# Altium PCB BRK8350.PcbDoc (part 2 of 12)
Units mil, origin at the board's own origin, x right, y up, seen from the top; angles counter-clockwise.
Board outline 9448.82 x 5905.51 mil, 8 copper layers (L1-TOP, L2-GND, L3-SIG, L4-GND, L5-PWR, L6-PWR, L7-GND, L8-BOT), stack 57.69 mil thick; 288 components, 543 nets, 1891 pads, 2032 vias.
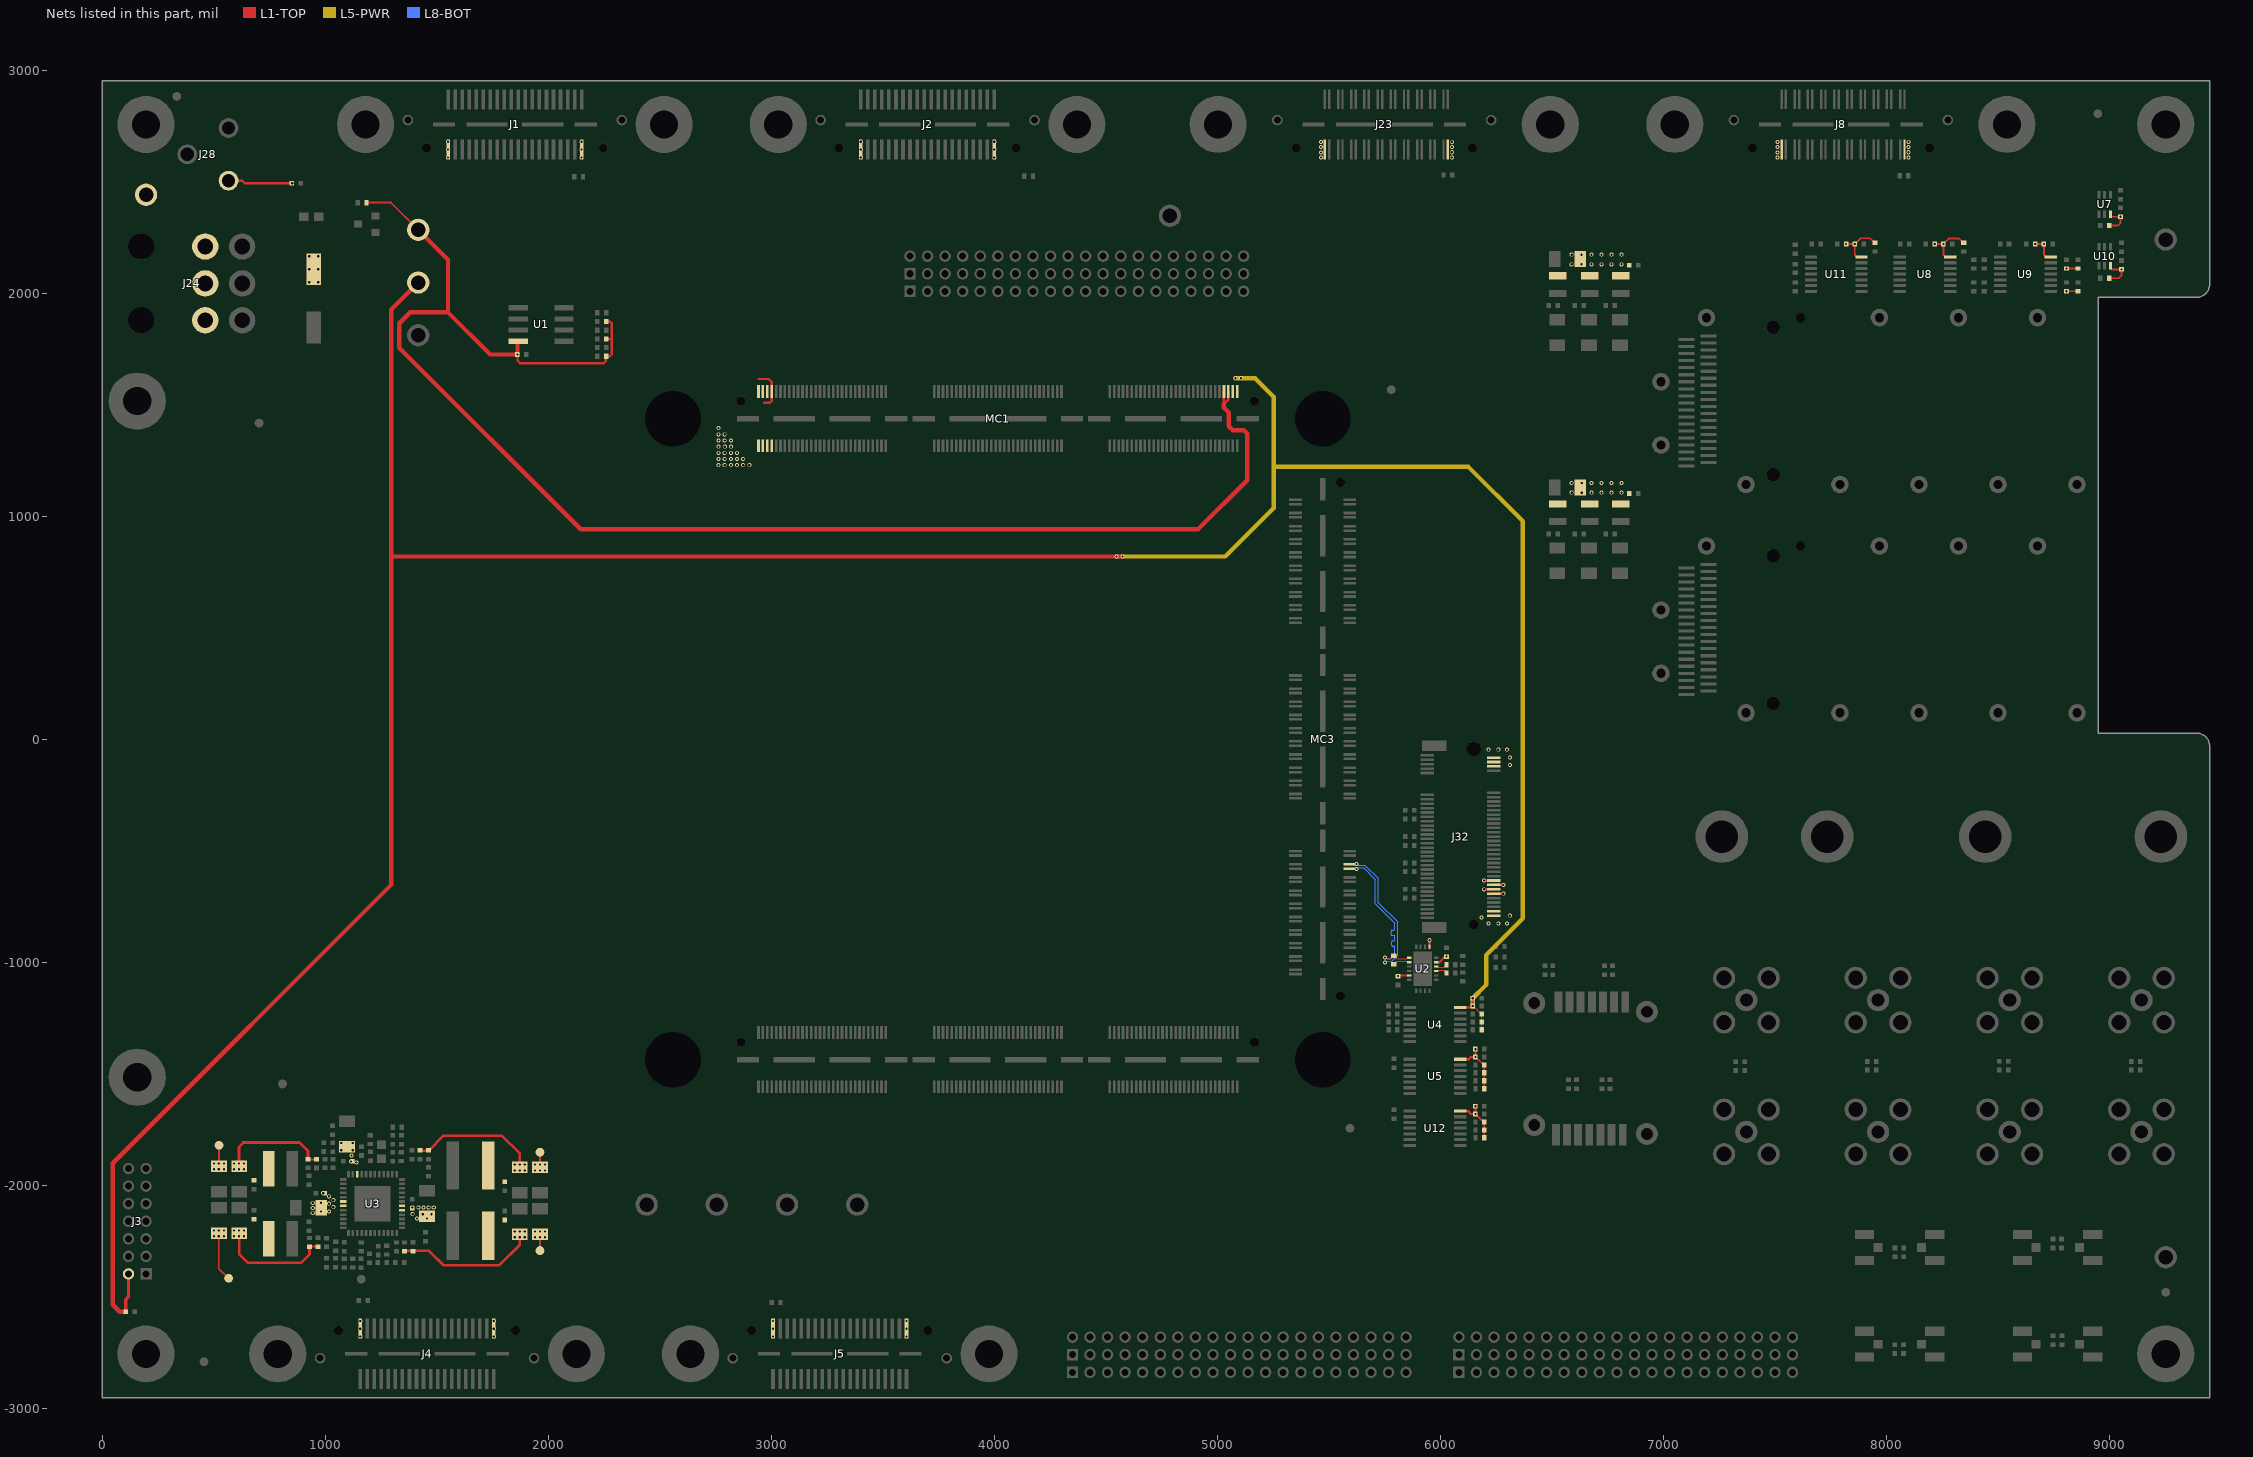
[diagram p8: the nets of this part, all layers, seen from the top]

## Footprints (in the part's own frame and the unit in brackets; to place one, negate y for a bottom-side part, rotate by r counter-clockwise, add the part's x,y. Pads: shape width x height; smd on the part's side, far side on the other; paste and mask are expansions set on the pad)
0455580003 [mm]
  round 3 hole 3 unplated: 0(-4.2,7.3) 0(4.2,7.3)
  round 3 hole 1.8: 1(-4.2,0) 2(0,0) 3(4.2,0) 4(-4.2,-4.2) 5(0,-4.2) 6(4.2,-4.2)
  silkscreen extent -7,1 7,14
9774025151R [mm]
  round 6 hole 3.7: 1(0,0)
9774025151R-NO-PASTE [mm]
  round 6 hole 3.7: 1(0,0)
CAPAE9083X70N [mm] "Aluminum Electrolytic Capacitor, Body 8.30x8.30x7.00mm, IPC Medium Density"
  rect 3.6x1.65 smd: 1(-3.325,0) 2(3.325,0)
  silkscreen extent -4.25,-4.25 4.25,4.25
CAPC1005X06A#1 [mm] "Chip Capacitor, 2-Leads, Body 1.00x0.50mm, OK custom footprint"
  rect 0.52x0.55 smd mask+0.051: 1(-0.51,0) 2(0.51,0)
CAPC1005X06A#2 [mm] "Chip Capacitor, 2-Leads, Body 1.00x0.50mm, OK custom footprint"
  rect 0.52x0.55 smd: 1(-0.51,0) 2(0.51,0)
CAPC1608N [mm] "Chip Capacitor, Body 1.6x0.8mm, IPC Medium Density"
  rect 1x1 smd: 1(-0.8,0) 2(0.8,0)
  silkscreen extent -0.8,-0.68 0.8,0.68, body extent -0.87,-0.48 0.87,0.48, height 0.85
CAPC3216N [mm] "Chip Capacitor, Body 3.2x1.6mm, IPC Medium Density"
  rect 1.3x1.8 smd: 1(-1.45,0) 2(1.45,0)
  silkscreen extent -1.2,-1.08 1.2,1.08, body extent -1.7,-0.9 1.7,0.9, height 1.35
CD1608-0603-PIN1-CATHODE [mm] "Chip Diode; Body 1.6 x 0.8 mm (LxW typ)"
  rect 1.1x1 smd: 1(-0.85,0) 2(0.85,0)
  silkscreen extent -1.58,-0.68 0.6,0.68
CIGT252010 [mm]
  rect 0.8x2 smd: 1(-1,0) 2(1,0)
CUI-PJ102A [mm] "2.1mm/5.5mm DC power jack"
  round 2.25 hole 1.5: 1(0,13.7) 2(0,7.7) 3(4.7,10.7)
  silkscreen extent -4.5,0 4.5,14.5
DCK-R-PDSO-G6 [mm]
  rect 0.35x0.85 smd: 1(-0.65,-1.1) 2(0,-1.1) 3(0.65,-1.1) 4(0.65,1.1) 5(0,1.1) 6(-0.65,1.1)
  silkscreen extent -1.01,-1.55 1.01,0.65
DSC557-05 [mm]
  rect 0.5x0.25 smd: 1(-2.5,0.75) 2(-2.5,0.25) 3(-2.5,-0.25) 4(-2.5,-0.75) 11(2.5,-0.75) 12(2.5,-0.25) 13(2.5,0.25) 14(2.5,0.75)
  rect 0.25x0.5 smd: 5(-1.25,-1.55) 6(-0.75,-1.55) 7(-0.25,-1.55) 8(0.25,-1.55) 9(0.75,-1.55) 10(1.25,-1.55) 15(1.25,1.55) 16(0.75,1.55) 17(0.25,1.55) 18(-0.25,1.55) 19(-0.75,1.55) 20(-1.25,1.55)
  rect 3.9x2.1 smd paste-10: PAD(0,0)
  silkscreen extent -2.9,-1.65 2.55,2
FID1MM/2MM-SS [mm] "Fiducial 1mm copper, 2mm soldermask, single-side"
  round 1 smd paste-0.5 mask+0.5: FID?(0,0)
HDR1X20-2MM [mm] "2mm 1x20 Header"
  rect 1.3x1.3 hole 0.8: 1(-19,0)
  round 1.3 hole 0.8: 2(-17,0) 3(-15,0) 4(-13,0) 5(-11,0) 6(-9,0) 7(-7,0) 8(-5,0) 9(-3,0) 10(-1,0) 11(1,0) 12(3,0) 13(5,0) 14(7,0) 15(9,0) 16(11,0) 17(13,0) 18(15,0) 19(17,0) 20(19,0)
  silkscreen extent -20,-1 20,1
HDR2X20-2MM [mm] "2mm 2x20 header"
  rect 1.3x1.3 hole 0.8: 1(-19,-1)
  round 1.3 hole 0.8: 2(-19,1) 3(-17,-1) 4(-17,1) 5(-15,-1) 6(-15,1) 7(-13,-1) 8(-13,1) 9(-11,-1) 10(-11,1) 11(-9,-1) 12(-9,1) 13(-7,-1) 14(-7,1) 15(-5,-1) 16(-5,1) 17(-3,-1) 18(-3,1) 19(-1,-1) 20(-1,1) 21(1,-1) 22(1,1) 23(3,-1) 24(3,1) 25(5,-1) 26(5,1) 27(7,-1) 28(7,1) 29(9,-1) 30(9,1) 31(11,-1) 32(11,1) 33(13,-1) 34(13,1) 35(15,-1) 36(15,1) 37(17,-1) 38(17,1) 39(19,-1) 40(19,1)
  silkscreen extent -20,-2 20,2
JSO-0515-01 [mil]
  round 0 hole 250 unplated: 1(0,0)
  Keep-Out Layer region: 0,-157.48 -60.27,-145.49 -111.36,-111.36 -145.49,-60.27 -157.48,0 -157.48,0 -145.49,60.27 -111.36,111.36 -60.27,145.49 0,157.48 0,157.48 60.27,145.49 111.36,111.36 145.49,60.27 157.48,0 157.48,0 145.49,-60.27 111.36,-111.36 60.27,-145.49 0,-157.48
M2-CONNECTOR_M-KEYING [mm] "M-2 Connector, 67-pin, M Keying"
  rect 1.2x2.75 smd mask+0.051: 1(-10.35,4.5) 1(10.35,4.5)
  rect 0.3x1.55 smd mask+0.051: 1(-9.25,5.275) 2(-9,-2.275) 3(-8.75,5.275) 4(-8.5,-2.275) 5(-8.25,5.275) 6(-8,-2.275) 7(-7.75,5.275) 8(-7.5,-2.275) 9(-7.25,5.275) 10(-7,-2.275) 11(-6.75,5.275) 12(-6.5,-2.275) 13(-6.25,5.275) 14(-6,-2.275) 15(-5.75,5.275) 16(-5.5,-2.275) 17(-5.25,5.275) 18(-5,-2.275) 19(-4.75,5.275) 20(-4.5,-2.275) 21(-4.25,5.275) 22(-4,-2.275) 23(-3.75,5.275) 24(-3.5,-2.275) 25(-3.25,5.275) 26(-3,-2.275) 27(-2.75,5.275) 28(-2.5,-2.275) 29(-2.25,5.275) 30(-2,-2.275) 31(-1.75,5.275) 32(-1.5,-2.275) 33(-1.25,5.275) 34(-1,-2.275) 35(-0.75,5.275) 36(-0.5,-2.275) 37(-0.25,5.275) 38(0,-2.275) 39(0.25,5.275) 40(0.5,-2.275) 41(0.75,5.275) 42(1,-2.275) 43(1.25,5.275) 44(1.5,-2.275) 45(1.75,5.275) 46(2,-2.275) 47(2.25,5.275) 48(2.5,-2.275) 49(2.75,5.275) 50(3,-2.275) 51(3.25,5.275) 52(3.5,-2.275) 53(3.75,5.275) 54(4,-2.275) 55(4.25,5.275) 56(4.5,-2.275) 57(4.75,5.275) 58(5,-2.275) 67(7.25,5.275) 68(7.5,-2.275) 69(7.75,5.275) 70(8,-2.275) 71(8.25,5.275) 72(8.5,-2.275) 73(8.75,5.275) 74(9,-2.275) 75(9.25,5.275)
  round 1.1 hole 1.1 unplated paste+0: MH(-10,0)
  round 1.6 hole 1.6 unplated paste+0: MH(10,0)
  silkscreen extent -11,-2.55 11,5.3
MAX3378EEUD+ [mm]
  rect 0.35x1.4 smd: 1(-1.95,-2.875) 2(-1.3,-2.875) 3(-0.65,-2.875) 4(0,-2.875) 5(0.65,-2.875) 6(1.3,-2.875) 7(1.95,-2.875) 8(1.95,2.875) 9(1.3,2.875) 10(0.65,2.875) 11(0,2.875) 12(-0.65,2.875) 13(-1.3,2.875) 14(-1.95,2.875)
  silkscreen extent -2.55,-3.83 2.55,2.27
MOLEX-67800-5005 [mm]
  rect 0.9x2.4 smd: 1(3.955,0.55) 2(2.685,0.55) 3(1.415,0.55) 4(0.145,0.55) 5(-1.125,0.55) 6(-2.395,0.55) 7(-3.665,0.55)
  round 2.5 hole 1.35: MH(-6.415,0.45) MH(6.415,-0.55)
  silkscreen extent -8.65,-3.9 8.6,2.85
MTG-3.2/6.5-PTH [mm] "Mounting hole, 3.2mm ID, 6.5mm OD, plated"
  round 6.5 hole 3.2: 1(0,0)
okLogo-23x5-2021 [mil] "Opal Kelly silkscreen logo (23mm x 5mm) - 2021 update"
  silkscreen extent -4,-15 672,100
PVQFN-48 [mm]
  rect 0.7x0.3 smd mask+0.051: 1(-3.35,2.75) 2(-3.35,2.25) 3(-3.35,1.75) 4(-3.35,1.25) 5(-3.35,0.75) 6(-3.35,0.25) 7(-3.35,-0.25) 8(-3.35,-0.75) 9(-3.35,-1.25) 10(-3.35,-1.75) 11(-3.35,-2.25) 12(-3.35,-2.75) 25(3.35,-2.75) 26(3.35,-2.25) 27(3.35,-1.75) 28(3.35,-1.25) 29(3.35,-0.75) 30(3.35,-0.25) 31(3.35,0.25) 32(3.35,0.75) 33(3.35,1.25) 34(3.35,1.75) 35(3.35,2.25) 36(3.35,2.75)
  rect 0.3x0.7 smd mask+0.051: 13(-2.75,-3.35) 14(-2.25,-3.35) 15(-1.75,-3.35) 16(-1.25,-3.35) 17(-0.75,-3.35) 18(-0.25,-3.35) 19(0.25,-3.35) 20(0.75,-3.35) 21(1.25,-3.35) 22(1.75,-3.35) 23(2.25,-3.35) 24(2.75,-3.35) 37(2.75,3.35) 38(2.25,3.35) 39(1.75,3.35) 40(1.25,3.35) 41(0.75,3.35) 42(0.25,3.35) 43(-0.25,3.35) 44(-0.75,3.35) 45(-1.25,3.35) 46(-1.75,3.35) 47(-2.25,3.35) 48(-2.75,3.35)
  rect 4.08x4.08 smd mask+0.051: PAD(0,0)
  silkscreen extent -3.89,-3.6 3.6,3.89
QSE-020-01-X-D-A-L-SYZYGY [mil] "0.80mm, 40 pin Surface Mount connectors with Ground Strip"
  rect 100x17 smd paste+0: 0(-317.45,0) 0(317.55,0)
  rect 185x17 smd paste+0: 0(-124.95,0) 0(125.05,0)
  round 255.91 hole 125.98: 1(-669.24,0) 1(669.34,0)
  rect 16x89.5 smd paste+0: 1(-299.25,-112.8) 2(-299.25,112.8) 3(-267.75,-112.8) 4(-267.75,112.8) 5(-236.25,-112.8) 6(-236.25,112.8) 7(-204.75,-112.8) 8(-204.75,112.8) 9(-173.25,-112.8) 10(-173.25,112.8) 11(-141.75,-112.8) 12(-141.75,112.8) 13(-110.25,-112.8) 14(-110.25,112.8) 15(-78.75,-112.8) 16(-78.75,112.8) 17(-47.25,-112.8) 18(-47.25,112.8) 19(-15.75,-112.8) 20(-15.75,112.8) 21(15.75,-112.8) 22(15.75,112.8) 23(47.25,-112.8) 24(47.25,112.8) 25(78.75,-112.8) 26(78.75,112.8) 27(110.25,-112.8) 28(110.25,112.8) 29(141.75,-112.8) 30(141.75,112.8) 31(173.25,-112.8) 32(173.25,112.8) 33(204.75,-112.8) 34(204.75,112.8) 35(236.25,-112.8) 36(236.25,112.8) 37(267.75,-112.8) 38(267.75,112.8) 39(299.25,-112.8) 40(299.25,112.8)
  round 47.24 hole 31.5 paste+0: MH(-479.48,-19.69) MH(479.58,-19.69)
  round 40.16 hole 40.16 unplated paste+0: MH(-396.25,105) MH(396.35,105)
  silkscreen extent -886,-157 885,276
QSFP28_RECEPTACLE_SFF-8679 [mm]
  rect 0.35x1.8 smd: 1(1.4,7.37) 2(2.2,7.37) 3(3,7.37) 4(3.8,7.37) 5(4.6,7.37) 6(5.4,7.37) 7(6.2,7.37) 8(7,7.37) 9(7.8,7.37) 10(8.6,7.37) 11(9.4,7.37) 12(10.2,7.37) 13(11,7.37) 14(11.8,7.37) 15(12.6,7.37) 16(13.4,7.37) 17(14.2,7.37) 18(15,7.37) 19(15.8,7.37) 20(15.4,9.88) 21(14.6,9.88) 22(13.8,9.88) 23(13,9.88) 24(12.2,9.88) 25(11.4,9.88) 26(10.6,9.88) 27(9.8,9.88) 28(9,9.88) 29(8.2,9.88) 30(7.4,9.88) 31(6.6,9.88) 32(5.8,9.88) 33(5,9.88) 34(4.2,9.88) 35(3.4,9.88) 36(2.6,9.88) 37(1.8,9.88) 38(1,9.88)
  round 1.55 hole 1.55 unplated: MH(0,0) MH(16.8,0)
  L1-TOP keep-out region: 16.3,-3.16 17.3,-3.16 17.3,-2.16 16.3,-2.16
  L1-TOP keep-out region: -0.5,-3.16 0.5,-3.16 0.5,-2.16 -0.5,-2.16
  silkscreen extent -0.8,-3 17.6,9.7
QSFP28_SINGLE_CAGE [mm]
  round 2 hole 1.05: 0(-1.1,3.1) 0(-1.1,-7.6) 0(-1.1,-16.6) 0(-1.1,-25.6) 0(-1.1,-34.6) 0(3.4,12.79) 0(10.6,12.79) 0(17.9,-21.1) 0(17.9,-12.1) 0(17.9,7.6) 0(17.9,-30.1)
  round 0 hole 1.05 unplated: 0(17.9,-3.1)
  L1-TOP keep-out region: -2.7,13.5 -2.7,-37 19.5,-37 19.5,13.5 16.5,13.5 16.5,11.1 18,11.1 18,-1.6 15.9,-1.6 15.9,-3.5 0.9,-3.5 0.9,-1.6 -1.2,-1.6 -1.2,11.1 0.3,11.1 0.3,13.5
  silkscreen extent -1.1,-48.2 17.9,12.9
QSH-020-01-X-D-DP-A-L-SYZYGY [mm]
  rect 2.54x0.43 smd mask+0.051: 0(-8.07,0) 0(8.06,0)
  rect 4.7x0.43 smd mask+0.051: 0(-3.18,0) 0(3.17,0)
  round 6.5 hole 3.2: 1(-18.909,0) 1(18.911,0)
  rect 0.28x2.27 smd mask+0.051: 1(-7.25,-2.87) 2(-7.25,2.87) 3(-6.75,-2.87) 4(-6.75,2.87) 5(-5.75,-2.87) 6(-5.75,2.87) 7(-5.25,-2.87) 8(-5.25,2.87) 9(-4.25,-2.87) 10(-4.25,2.87) 11(-3.75,-2.87) 12(-3.75,2.87) 13(-2.75,-2.87) 14(-2.75,2.87) 15(-2.25,-2.87) 16(-2.25,2.87) 17(-1.25,-2.87) 18(-1.25,2.87) 19(-0.75,-2.87) 20(-0.75,2.87) 21(0.25,-2.87) 22(0.25,2.87) 23(0.75,-2.87) 24(0.75,2.87) 25(1.75,-2.87) 26(1.75,2.87) 27(2.25,-2.87) 28(2.25,2.87) 29(3.25,-2.87) 30(3.25,2.87) 31(3.75,-2.87) 32(3.75,2.87) 33(4.75,-2.87) 34(4.75,2.87) 35(5.25,-2.87) 36(5.25,2.87) 37(6.25,-2.87) 38(6.25,2.87) 39(6.75,-2.87) 40(6.75,2.87)
  round 1.2 hole 0.8 paste+0 mask+0.076: MH(-12.18,-0.5) MH(12.18,-0.5)
  round 1.02 hole 1.02 unplated paste+0: MH(-10.07,2.67) MH(10.07,2.67)
  silkscreen extent -25,-3.99 25,7.01
QTH-060-01-X-D-DP-A [mm] "2mm 1x20 Header"
  rect 2.54x0.64 smd: 0(-28.445,0) 0(-11.555,0) 0(-8.445,0) 0(8.445,0) 0(11.555,0) 0(28.445,0)
  rect 4.7x0.64 smd: 0(-23.175,0) 0(-16.825,0) 0(-3.175,0) 0(3.175,0) 0(16.825,0) 0(23.175,0)
  rect 0.3x1.45 smd: 1(-27.25,3.09) 2(-27.25,-3.09) 3(-26.75,3.09) 4(-26.75,-3.09) 5(-25.75,3.09) 6(-25.75,-3.09) 7(-25.25,3.09) 8(-25.25,-3.09) 9(-24.25,3.09) 10(-24.25,-3.09) 11(-23.75,3.09) 12(-23.75,-3.09) 13(-22.75,3.09) 14(-22.75,-3.09) 15(-22.25,3.09) 16(-22.25,-3.09) 17(-21.25,3.09) 18(-21.25,-3.09) 19(-20.75,3.09) 20(-20.75,-3.09) 21(-19.75,3.09) 22(-19.75,-3.09) 23(-19.25,3.09) 24(-19.25,-3.09) 25(-18.25,3.09) 26(-18.25,-3.09) 27(-17.75,3.09) 28(-17.75,-3.09) 29(-16.75,3.09) 30(-16.75,-3.09) 31(-16.25,3.09) 32(-16.25,-3.09) 33(-15.25,3.09) 34(-15.25,-3.09) 35(-14.75,3.09) 36(-14.75,-3.09) 37(-13.75,3.09) 38(-13.75,-3.09) 39(-13.25,3.09) 40(-13.25,-3.09) 41(-7.25,3.09) 42(-7.25,-3.09) 43(-6.75,3.09) 44(-6.75,-3.09) 45(-5.75,3.09) 46(-5.75,-3.09) 47(-5.25,3.09) 48(-5.25,-3.09) 49(-4.25,3.09) 50(-4.25,-3.09) 51(-3.75,3.09) 52(-3.75,-3.09) 53(-2.75,3.09) 54(-2.75,-3.09) 55(-2.25,3.09) 56(-2.25,-3.09) 57(-1.25,3.09) 58(-1.25,-3.09) 59(-0.75,3.09) 60(-0.75,-3.09) 61(0.25,3.09) 62(0.25,-3.09) 63(0.75,3.09) 64(0.75,-3.09) 65(1.75,3.09) 66(1.75,-3.09) 67(2.25,3.09) 68(2.25,-3.09) 69(3.25,3.09) 70(3.25,-3.09) 71(3.75,3.09) 72(3.75,-3.09) 73(4.75,3.09) 74(4.75,-3.09) 75(5.25,3.09) 76(5.25,-3.09) 77(6.25,3.09) 78(6.25,-3.09) 79(6.75,3.09) 80(6.75,-3.09) 81(12.75,3.09) 82(12.75,-3.09) 83(13.25,3.09) 84(13.25,-3.09) 85(14.25,3.09) 86(14.25,-3.09) 87(14.75,3.09) 88(14.75,-3.09) 89(15.75,3.09) 90(15.75,-3.09) 91(16.25,3.09) 92(16.25,-3.09) 93(17.25,3.09) 94(17.25,-3.09) 95(17.75,3.09) 96(17.75,-3.09) 97(18.75,3.09) 98(18.75,-3.09) 99(19.25,3.09) 100(19.25,-3.09) 101(20.25,3.09) 102(20.25,-3.09) 103(20.75,3.09) 104(20.75,-3.09) 105(21.75,3.09) 106(21.75,-3.09) 107(22.25,3.09) 108(22.25,-3.09) 109(23.25,3.09) 110(23.25,-3.09) 111(23.75,3.09) 112(23.75,-3.09) 113(24.75,3.09) 114(24.75,-3.09) 115(25.25,3.09) 116(25.25,-3.09) 117(26.25,3.09) 118(26.25,-3.09) 119(26.75,3.09) 120(26.75,-3.09)
  round 1.02 hole 1.02 unplated: MH(-29.24,2.03) MH(29.24,2.03)
  silkscreen extent -30.05,-3.05 30.05,3.05
QTH-090-01-X-D [mm]
  rect 2.54x0.64 smd: 0(-28.445,0) 0(-11.555,0) 0(-8.445,0) 0(8.445,0) 0(11.555,0) 0(28.445,0)
  rect 4.7x0.64 smd: 0(-23.175,0) 0(-16.825,0) 0(-3.175,0) 0(3.175,0) 0(16.825,0) 0(23.175,0)
  rect 0.3x1.45 smd: 1(-27.25,3.09) 2(-27.25,-3.09) 3(-26.75,3.09) 4(-26.75,-3.09) 5(-26.25,3.09) 6(-26.25,-3.09) 7(-25.75,3.09) 8(-25.75,-3.09) 9(-25.25,3.09) 10(-25.25,-3.09) 11(-24.75,3.09) 12(-24.75,-3.09) 13(-24.25,3.09) 14(-24.25,-3.09) 15(-23.75,3.09) 16(-23.75,-3.09) 17(-23.25,3.09) 18(-23.25,-3.09) 19(-22.75,3.09) 20(-22.75,-3.09) 21(-22.25,3.09) 22(-22.25,-3.09) 23(-21.75,3.09) 24(-21.75,-3.09) 25(-21.25,3.09) 26(-21.25,-3.09) 27(-20.75,3.09) 28(-20.75,-3.09) 29(-20.25,3.09) 30(-20.25,-3.09) 31(-19.75,3.09) 32(-19.75,-3.09) 33(-19.25,3.09) 34(-19.25,-3.09) 35(-18.75,3.09) 36(-18.75,-3.09) 37(-18.25,3.09) 38(-18.25,-3.09) 39(-17.75,3.09) 40(-17.75,-3.09) 41(-17.25,3.09) 42(-17.25,-3.09) 43(-16.75,3.09) 44(-16.75,-3.09) 45(-16.25,3.09) 46(-16.25,-3.09) 47(-15.75,3.09) 48(-15.75,-3.09) 49(-15.25,3.09) 50(-15.25,-3.09) 51(-14.75,3.09) 52(-14.75,-3.09) 53(-14.25,3.09) 54(-14.25,-3.09) 55(-13.75,3.09) 56(-13.75,-3.09) 57(-13.25,3.09) 58(-13.25,-3.09) 59(-12.75,3.09) 60(-12.75,-3.09) 61(-7.25,3.09) 62(-7.25,-3.09) 63(-6.75,3.09) 64(-6.75,-3.09) 65(-6.25,3.09) 66(-6.25,-3.09) 67(-5.75,3.09) 68(-5.75,-3.09) 69(-5.25,3.09) 70(-5.25,-3.09) 71(-4.75,3.09) 72(-4.75,-3.09) 73(-4.25,3.09) 74(-4.25,-3.09) 75(-3.75,3.09) 76(-3.75,-3.09) 77(-3.25,3.09) 78(-3.25,-3.09) 79(-2.75,3.09) 80(-2.75,-3.09) 81(-2.25,3.09) 82(-2.25,-3.09) 83(-1.75,3.09) 84(-1.75,-3.09) 85(-1.25,3.09) 86(-1.25,-3.09) 87(-0.75,3.09) 88(-0.75,-3.09) 89(-0.25,3.09) 90(-0.25,-3.09) 91(0.25,3.09) 92(0.25,-3.09) 93(0.75,3.09) 94(0.75,-3.09) 95(1.25,3.09) 96(1.25,-3.09) 97(1.75,3.09) 98(1.75,-3.09) 99(2.25,3.09) 100(2.25,-3.09) 101(2.75,3.09) 102(2.75,-3.09) 103(3.25,3.09) 104(3.25,-3.09) 105(3.75,3.09) 106(3.75,-3.09) 107(4.25,3.09) 108(4.25,-3.09) 109(4.75,3.09) 110(4.75,-3.09) 111(5.25,3.09) 112(5.25,-3.09) 113(5.75,3.09) 114(5.75,-3.09) 115(6.25,3.09) 116(6.25,-3.09) 117(6.75,3.09) 118(6.75,-3.09) 119(7.25,3.09) 120(7.25,-3.09) 121(12.75,3.09) 122(12.75,-3.09) 123(13.25,3.09) 124(13.25,-3.09) 125(13.75,3.09) 126(13.75,-3.09) 127(14.25,3.09) 128(14.25,-3.09) 129(14.75,3.09) 130(14.75,-3.09) 131(15.25,3.09) 132(15.25,-3.09) 133(15.75,3.09) 134(15.75,-3.09) 135(16.25,3.09) 136(16.25,-3.09) 137(16.75,3.09) 138(16.75,-3.09) 139(17.25,3.09) 140(17.25,-3.09) 141(17.75,3.09) 142(17.75,-3.09) 143(18.25,3.09) 144(18.25,-3.09) 145(18.75,3.09) 146(18.75,-3.09) 147(19.25,3.09) 148(19.25,-3.09) 149(19.75,3.09) 150(19.75,-3.09) 151(20.25,3.09) 152(20.25,-3.09) 153(20.75,3.09) 154(20.75,-3.09) 155(21.25,3.09) 156(21.25,-3.09) 157(21.75,3.09) 158(21.75,-3.09) 159(22.25,3.09) 160(22.25,-3.09) 161(22.75,3.09) 162(22.75,-3.09) 163(23.25,3.09) 164(23.25,-3.09) 165(23.75,3.09) 166(23.75,-3.09) 167(24.25,3.09) 168(24.25,-3.09) 169(24.75,3.09) 170(24.75,-3.09) 171(25.25,3.09) 172(25.25,-3.09) 173(25.75,3.09) 174(25.75,-3.09) 175(26.25,3.09) 176(26.25,-3.09) 177(26.75,3.09) 178(26.75,-3.09) 179(27.25,3.09) 180(27.25,-3.09)
  round 1.02 hole 1.02 unplated: MH(-29.24,2.03) MH(29.24,2.03)
  silkscreen extent -30.05,-3.05 30.05,3.05
RESC1005X06A [mm] "Chip Resistor, 2-Leads, Body 1.00x0.50mm, OK custom footprint"
  rect 0.5x0.6 smd mask+0.051: 1(-0.5,0) 2(0.5,0)
SMA [mil] "PCB-mount SMA connector"
  round 100 hole 59: 1(0,0)
  round 100 hole 67: 2(-100,100) 2(-100,-100) 2(100,100) 2(100,-100)
  Top Overlay keep-out lines w10: 170,-170 170,170 -170,170 -170,-170 170,-170
  silkscreen extent -170,-170 170,170
SO-G8 [mm] "Small Outline; 8 Leads; Body Width 3.9 mm; Pitch 1.27 mm"
  rect 0.6x2.2 smd: 1(-1.905,-2.6) 2(-0.635,-2.6) 3(0.635,-2.6) 4(1.905,-2.6) 5(1.905,2.6) 6(0.635,2.6) 7(-0.635,2.6) 8(-1.905,2.6)
  silkscreen extent -2.45,-3.7 2.45,1.95
SOT23-95P240X110 [mm] "SOT-23; 3 Leads; Body 3.0 x 2.6 mm, inc. leads (LxW max)"
  rect 0.8x0.9 smd: 1(-0.95,-1) 2(0.95,-1) 3(0,1)
  silkscreen extent -1.53,-1.45 1.54,0.77
TP-PTH-65/100#1 [mil] "Test point, plated through-hole, 65/100mil"
  round 100 hole 65: 1(0,0)
TP-PTH-65/100#2 [mil] "Test point, plated through-hole, 65/100mil"
  round 100 hole 65: 1(0,0.49)
TP-PTH-65/100#3 [mil] "Test point, plated through-hole, 65/100mil"
  round 100 hole 65: 1(-4.91,0.44)
TP-SMD40 [mm] "Test point, surface-mount, 40mil"
  round 1 smd paste-2: 1(0,0)
UFL-R-SMT-1 [mm] "U.FL surface-mount coaxial connector"
  rect 1x1.05 smd paste+0: 1(0,-1.525)
  rect 1.05x2.2 smd paste+0: 2(-1.475,0) 2(1.475,0)
  silkscreen extent -1.3,-1.3 1.3,1.3
VLS4012CX [mm]
  rect 1.3x4 smd: 1(-1.35,0) 2(1.35,0)
  silkscreen extent -0.45,-2.2 0.45,2.2
XAL60XX [mm]
  rect 1.43x5.5 smd: 1(-2.02,0) 2(2.02,0)
  silkscreen extent -3.25,-3.35 3.25,3.35
XILINX-JTAG [mm] "2mm 2x7 header"
  rect 1.3x1.3 hole 0.8: 1(-6,-1)
  round 1.3 hole 0.8: 2(-6,1) 3(-4,-1) 4(-4,1) 5(-2,-1) 6(-2,1) 7(0,-1) 8(0,1) 9(2,-1) 10(2,1) 11(4,-1) 12(4,1) 13(6,-1) 14(6,1)
  silkscreen extent -8.32,-3.15 8.32,3.15

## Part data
*1: library part OKLOGO, partnumber=ALIGNI_IGNORE
C1 C6 C7 C8 C9 C10 C11 C12 C13 C14 C15 C16 C17 C18 C19 C20 C21 C22 C23 C24 C25 C26 C27 C28 C29 C90 C92 C95 C102 C104 C107 C112 C114: library part 000070, Manufacturer=Kemet, Manufacturer_PN=C0402C104K8PACTU, ValueFloat=1E-7, x_tolerance=10
C2: library part 000070, Manufacturer=Kemet, Manufacturer_PN=C0402C104K8PACTU, ValueFloat=1E-7, x_max_operating_temp=85, x_min_operating_temp=-55, x_tolerance=10
C3 C5 C100 C101: library part 001073, Manufacturer=Kemet, partnumber=000070, ValueFloat=1E-7, x_tolerance=10
C4 C88: library part 000295, "Ceramic Capacitor", Manufacturer=Kemet, Tolerance (%)=10, ValueFloat=1E-8
C30: library part 001346, "Ceramic capacitor", Manufacturer="Taiyo Yuden", Tolerance (%)=20, ValueFloat=1E-5
C31: library part 000824, "Ceramic capacitor", Manufacturer="Taiyo Yuden", Tolerance (%)=20, ValueFloat=4.7E-6
C32: library part 001926, Manufacturer=TDK, ValueFloat=3.3E-6, x_tolerance=20
C33 C46 C57: library part 001172, "Ceramic Capacitor", Manufacturer=TDK, Tolerance (%)=20, ValueFloat=2.2E-5, Voltage=35V, x_voltage-rating=35
C34 C37 C47 C58: library part 001073, "Ceramic capacitor", Manufacturer="Taiyo Yuden", Tolerance (%)=10, ValueFloat=1E-7, Voltage=25V
C35 C38 C43 C45 C48 C51 C55 C56 C59 C63 C66 C67: library part 000070, "Ceramic capacitor", Manufacturer=Kemet, Tolerance (%)=10, ValueFloat=1E-7
C36: library part 001532, "Polarized", Manufacturer=Panasonic, ValueFloat=0.00022, Voltage=25V, x_tolerance=20, x_voltage-rating=25
C39 C40 C49 C50 C60 C61 C68 C69: library part 001284, "Ceramic capacitor", Manufacturer="Taiyo Yuden", Tolerance (%)=10, ValueFloat=2.2E-5
C41 C52: library part 001004, Manufacturer=Kemet, Manufacturer_PN=C0402C560J5GACTU, ValueFloat=5.6E-11, x_temperature_characteristic=C0G, x_tolerance=5
C42 C53 C64 C72: library part 000930, "Ceramic capacitor", Manufacturer=Kemet, Tolerance (%)=10, ValueFloat=4.7E-9
C44 C54 C65 C74: library part 000807, "Ceramic capacitor", Manufacturer=Kemet, Tolerance (%)=5, ValueFloat=2.2E-11
C62 C70: library part 001004, "Ceramic capacitor", Manufacturer=Kemet, Tolerance (%)=5, ValueFloat=5.6E-11
C71: library part 000400, Manufacturer=Kemet, Manufacturer_PN=C0402C101J5GACTU, ValueFloat=1E-10
C73: library part 000962, "Ceramic capacitor", Manufacturer=Murata, Tolerance (%)=3.125, ValueFloat=5E-12
C75 C76 C86 C87 C89 C97 C98 C108 C109 C115 C117 C118: library part 000070, Manufacturer=Kemet, ValueFloat=1E-7, x_tolerance=10
C77 C78 C79 C80 C81 C82 C83 C84: library part 000333, Manufacturer="Taiyo Yuden", Manufacturer_PN=LMK105BJ224KV-F, ValueFloat=2.2E-7, x_temperature_characteristic=X5R, x_tolerance=10
C85 C96 C99 C110 C116 C119: library part 000480, Manufacturer="Taiyo Yuden", ValueFloat=1E-6, x_tolerance=10
C91 C93 C94 C103 C105 C106 C111 C113: library part 001284, Manufacturer="Taiyo Yuden", Manufacturer_PN=LMK316AB7226KL-TR, ValueFloat=2.2E-5, x_temperature_characteristic=X7R, x_tolerance=10
D1: library part 001433, "LED", Manufacturer=Dialight, Manufacturer_PN=598-8070-107F
FID1 FID2 FID3 FID4 FID5 FID6 FID7 FID8: "PCB fiducial", partnumber=ALIGNI_IGNORE
J1 J2 J4 J5: library part 001604, "0.8mm hi-speed, high-density header (male)", Manufacturer=Samtec
J3: library part 000541, "2mm header, shrouded", Manufacturer=Molex
J6 J7 J9 J10 J11 J12 J13 J14: library part 000974, "Straight SMA PCB Mount", Manufacturer=Amphenol, Manufacturer_PN=901-144-8RFX
J8 J23: library part 000694, "0.5mm Double Row High Speed Socket Assembly", Manufacturer=Samtec
J15 J16 J17 J18 J19 J20 J21 J22: library part 001335, "U.FL surface-mount coaxial connector", Manufacturer=Hirose, Manufacturer_PN=U.FL-R-SMT-1
J24: library part 001950, Manufacturer=Molex
J26 J27: library part 000988, "SATA 7-pin receptacle", Manufacturer=Molex
J28: library part DCPOWER, "DC power connector - high current", Manufacturer="CUI Inc.", partnumber=000356
J30 J31: library part 001782, Manufacturer=Amphenol
J32: library part 001722, Manufacturer=Amphenol
JSO1 JSO2 JSO3 JSO4: library part 001879, "Mounting hole", Manufacturer=Samtec, Manufacturer_PN=JSO-0515-01
L1 L2: library part 001543, "Power inductor, 2.2uH, 7A, 12.7mOhm", Manufacturer=Coilcraft, Tolerance (%)=20, ValueFloat=2.2E-6
L3 L4: library part 002384, Manufacturer=TDK, ValueFloat=2.2E-6, x_tolerance=20
L5 L6 L7 L8 L9 L10: library part 002331, "Thin Film, 1uH, 3.1A, 50mOhm, Unshielded", Manufacturer="Samsung Electro-Mechanics", Tolerance (%)=20, ValueFloat=1E-6
MC1 MC2: library part 000876, "0.5mm Double Row High Speed Socket Assembly", Manufacturer=Samtec
MC1A MC2A MC2B: library part 000583, Manufacturer=Molex
MC1B MC2C MC2D: library part 001334, Manufacturer=3M, Manufacturer_PN=951120-8622-AR
MC3: library part 001769, Manufacturer=Samtec
MH1 MH2 MH5 MH6 MH7 MH8: "Mounting hole", partnumber=ALIGNI_IGNORE
Q1: library part 001237, "N-Channel MOSFET", Manufacturer="Fairchild Semiconductor", Manufacturer_PN=FDN337N, PackageDocument=1995/1996
QSFP1 QSFP2: library part 001781, Manufacturer=Amphenol, Manufacturer_PN=U95-T111-1001
R1: library part 001549, "Thick-film resistor", Manufacturer=Vishay, Tolerance (%)=1, ValueFloat=210000
R2: library part 001550, "Thick-film resistor", Manufacturer=Vishay, Tolerance (%)=1, ValueFloat=84500
R3 R4 R5 R6 R7 R8 R17 R20 R24 R29: library part 001521, Manufacturer=Vishay, Manufacturer_PN=CRCW040210K0FKED, ValueFloat=10000, x_tolerance=1
R9: library part Resistor, "Thick-film resistor", Manufacturer=Yageo, partnumber=001908, ValueFloat=8870.0
R10: library part Resistor, "Thick-film resistor", Manufacturer=Yageo, partnumber=001909, ValueFloat=6980.0
R11: library part 000827, Manufacturer=Vishay, Manufacturer_PN=CRCW0402100RFKED, ValueFloat=100, x_tolerance=1
R12: library part 001551, "Thick-film resistor", Manufacturer=Vishay, Tolerance (%)=1, ValueFloat=34000
R13: library part 001035, "Thick-film resistor", Manufacturer=Vishay, Tolerance (%)=1, ValueFloat=49900
R14 R15 R31 R58 R63 R64 R66: library part 001521, "Thick-film resistor", Manufacturer=Vishay, Tolerance (%)=1, ValueFloat=10000
R16 R19 R22: library part 001091, Manufacturer=Vishay, Manufacturer_PN=CRCW040231K6FKED, ValueFloat=31600, x_tolerance=1
R18 R21 R23 R27: library part 001121, "Thick-film resistor", Manufacturer=Vishay, Tolerance (%)=1, ValueFloat=15000
R25: library part 001122, Manufacturer=Vishay, ValueFloat=39200, x_tolerance=1
R26: library part 001157, Manufacturer=Vishay, Manufacturer_PN=CRCW040252K3FKED, ValueFloat=52300, x_tolerance=1
R28: library part 001618, "Thick-film resistor", Manufacturer=Vishay, Tolerance (%)=1, ValueFloat=374000
R30: library part 001162, "Thick-film resistor", Manufacturer=Vishay, Tolerance (%)=1, ValueFloat=2000
R32 R33 R34 R35 R36 R37 R38 R39 R41 R42 R43 R44 R45 R46 R47 R48 R49 R50 R51 R52 R53 R54 R55 R56 R57: library part 001008, Manufacturer=Vishay, ValueFloat=4750, x_tolerance=1
R40 R61 R62 R65: library part 001713, Manufacturer=Vishay, Manufacturer_PN=CRCW04020000Z0EDC, ValueFloat=0, x_tolerance=1
R59 R60: library part 001715, Manufacturer=Vishay, Manufacturer_PN=CRCW040249R9FKEDC, ValueFloat=49.9, x_tolerance=1
SO1 SO2 SO3 SO4: library part 9774025151R, "SMT steel standoff, M2.5 threads, 2.5 mm stack height", Manufacturer=Wurth, partnumber=001726
TP1 TP2 TP3 TP4 TP6 TP7 TP9 TP10 TP12 TP13 TP15: library part TP-PTH-65/100, "Test point, plated through-hole, 65/100mil", partnumber=ALIGNI_IGNORE
TP17 TP18 TP19 TP20: library part TESTPOINT-SMD40, "Test point, surface-mount, 40mil"
TP21: "Test point, surface-mount, 40mil"
U1: library part 000842, Manufacturer=Microchip
U2: library part 002422, "Crystal-less Four Output PCIe Clock Generator", Manufacturer=Microchip
U3: library part 001511, "4-channel switching regulator with PMBus", Manufacturer="Texas Instruments"
U4 U5 U8 U9 U11 U12: library part 000178, Manufacturer=Maxim
U7 U10: library part 002140, "Level Translator, 0.65V - 3.6V, Direction Control", Manufacturer="Texas Instruments"

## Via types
v1: diameter 18, hole 10, L1-TOP to L8-BOT, tented both sides, 2032 vias

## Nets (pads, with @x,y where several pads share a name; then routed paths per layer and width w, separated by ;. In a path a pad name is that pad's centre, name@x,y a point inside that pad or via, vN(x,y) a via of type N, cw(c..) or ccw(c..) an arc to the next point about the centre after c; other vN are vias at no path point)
"100MHZ _REFCLK_P": MC3.85 R11.2 U2.16 | length 701.4
  L1-TOP w4.2: v1(5751.97,-1001.41) 5755.7,-1001.41 5760.65,-996.46 5779.17,-996.46 5781.63,-998.92 5781.63,-1002.1 5789.37,-1009.84 R11.2@5791.34,-1009.84 5793.31,-1009.84 5801.05,-1002.1 5801.05,-998.92 5803.51,-996.46 5826.87,-996.46 5850.03,-996.46 5850.75,-997.18 5857.41,-997.18 U2.16@5860.24,-1000
  L8-BOT w4.2: v1(5623.48,-559.51) 5627.21,-559.51 5632.26,-564.55 5661.14,-564.55 5721.26,-624.67 5721.26,-733.07 5807.88,-819.69 5807.88,-969.79 5781.2,-996.46 5760.65,-996.46 5755.7,-1001.41 v1(5751.97,-1001.41)
100MHZ_OSC_N: R61.2 U2.7 | length 53.1
  L1-TOP w4.2: U2.7@5982.28,-1039.37 5985.1,-1036.55 5991.77,-1036.55 5992.49,-1035.83 6003.84,-1035.83 6017.36,-1035.83 6019.82,-1038.29 6019.82,-1040.43 R61.2@6027.56,-1048.17
100MHZ_OSC_P: R40.2 U2.8 | length 53.1
  L1-TOP w4.2: U2.8@5982.28,-1019.69 5985.1,-1022.51 5991.77,-1022.51 5992.49,-1023.23 5998.62,-1023.23 6017.36,-1023.23 6019.82,-1020.77 6019.82,-1018.63 R40.2@6027.56,-1010.89
100MHZ_REFCLK_N: MC3.87 R11.1 U2.15 | length 701.4
  L1-TOP w4.2: v1(5751.97,-978.91) 5755.7,-978.91 5760.65,-983.86 5779.17,-983.86 5781.63,-981.4 5781.63,-978.21 5789.37,-970.47 R11.1@5791.34,-970.47 5793.31,-970.47 5801.05,-978.21 5801.05,-981.4 5803.51,-983.86 5832.09,-983.86 5850.03,-983.86 5850.75,-983.14 5857.41,-983.14 U2.15@5860.24,-980.32
  L8-BOT w4.2: v1(5623.48,-582.19) 5627.21,-582.19 5632.26,-577.15 5655.92,-577.15 5708.66,-629.89 5708.66,-738.29 5795.28,-824.91 5795.28,-851.21 cw(c5790.44,-851.21) 5790.44,-856.05 5784.05,-856.05 ccw(c5784.05,-860.89) 5779.21,-860.89 5779.21,-875.41 ccw(c5784.05,-875.41) 5784.05,-880.25 5790.44,-880.25 cw(c5790.44,-885.09) 5795.28,-885.09 5795.28,-899.61 cw(c5790.44,-899.61) 5790.44,-904.45 5786.99,-904.45 ccw(c5786.99,-909.29) 5782.15,-909.29 5782.15,-923.81 ccw(c5786.99,-923.81) 5786.99,-928.65 5790.44,-928.65 cw(c5790.44,-933.49) 5795.28,-933.49 5795.28,-954.6 5795.28,-964.57 5775.99,-983.86 5760.65,-983.86 5755.7,-978.91 v1(5751.97,-978.91)
+1.8VDD: C1.2 C76.2 C85.2 J3.2 MC1.177 MC1.179 R35.2 R36.2 R37.2 TP7.1 U4.14 | length 13880.7
  L1-TOP w5: v1(6145.28,-1196.85) 6145.28,-1197.44 6152.01,-1204.18 6155.3,-1204.18 6175.09,-1223.97 6178.7,-1223.97 6185.04,-1230.31 R35.2@6185.04,-1232.28 R36.2@6185.04,-1267.72 R37.2@6185.04,-1303.15
  L1-TOP w10: U4.14@6089.57,-1202.76 6139.96,-1202.76 C76.2@6145.28,-1197.44 ; v1(6145.28,-1196.85) v1(6145.28,-1161.42)
  L1-TOP w15: C1.2@105.21,-2566.93 105.21,-2512.9 118.11,-2500 J3.2@118.11,-2397.64
  L1-TOP w20: C1.2@105.21,-2566.93 78.74,-2566.93 47.24,-2535.43 47.24,-1901.57 1295.28,-653.54 1295.28,818.9 ; TP7.1@1417.32,2047.24 1295.28,1925.2 1295.28,818.9 ; v1(4574.8,818.9) v1(4547.24,818.9) 1295.28,818.9
  L5-PWR w20: v1(4547.24,818.9) v1(4574.8,818.9) 5035.43,818.9 5251.97,1035.43 5251.97,1220.47 ; v1(5081.1,1618.35) v1(5106.5,1618.35) 5169.05,1618.35 5251.97,1535.43 5251.97,1220.47 ; v1(6145.28,-1196.85) v1(6145.28,-1161.42) 6204.72,-1101.97 6204.72,-968.5 6370.08,-803.15 6370.08,976.38 6125.98,1220.47 5251.97,1220.47
+3.3V_M.2: C4.2 C48.2 C49.2 C50.2 C52.2 C88.2 C115.2 C116.2 C118.2 C119.2 J32.2 J32.4 J32.12 J32.14 J32.16 J32.18 J32.70 J32.72 J32.74 L2.2 R19.2 R38.2 R39.2 R41.2 R54.2 R55.2 R56.2 R57.2 TP18.1 U2.9 U2.11 U2.19 U5.14 U12.14 | length 1454.2
  L1-TOP w8: C50.2@1963.1,-1920.15 TP18.1@1963.1,-1851.87 ; U2.11@5950.79,-931.1 v1(5950.79,-901.57) ; R57.2@6196.85,-1787.4 R56.2@6196.85,-1751.97 6196.85,-1714.57 6191.01,-1708.72 6186.12,-1708.72 6165.33,-1687.93 6163.32,-1687.93 C118.2@6157.09,-1681.69 ; R54.2@6196.85,-1566.93 R41.2@6196.85,-1531.5 R39.2@6196.85,-1496.06 6196.85,-1458.66 6191.01,-1452.82 6186.34,-1452.82 6165.55,-1432.02 6163.32,-1432.02 C115.2@6157.09,-1425.79 ; C118.2@6157.09,-1681.69 v1(6157.09,-1681.1) C118.2@6157.09,-1681.69 ; C115.2@6157.09,-1425.79 v1(6157.09,-1425.2) C115.2@6157.09,-1425.79
  L1-TOP w10: v1(5810.1,-1062.06) 5813.03,-1059.13 5860.16,-1059.13 U2.19@5860.24,-1059.06 ; U2.9@5982.28,-1000 5995.58,-1000 6015.54,-980.04 6022.32,-980.04 v1(6027.56,-974.8) ; U12.14@6089.57,-1667.32 6123.49,-1667.32 6137.27,-1681.1 v1(6157.09,-1681.1) v1(6157.09,-1645.67) ; U5.14@6089.57,-1435.04 6126.97,-1435.04 6136.81,-1425.2 v1(6157.09,-1425.2) v1(6157.09,-1389.76)
  L1-TOP w11: v1(6196.39,-673.23) J32.14@6239.17,-673.23 ; v1(6196.39,-633.86) J32.18@6239.17,-633.86 ; J32.12@6239.17,-692.91 v1(6281.96,-692.91) ; J32.16@6239.17,-653.54 v1(6281.96,-653.54)
  L1-TOP w12: R19.2@1424.74,-1845.95 1425.14,-1845.55 1462.74,-1845.55 1530.85,-1777.45 1791.38,-1777.45 1872.57,-1858.64 C49.2@1872.57,-1920.15
  L1-TOP w16: C50.2@1963.1,-1920.15 C50.2@1963.71,-1920.77
  other v1: 1850.27,-1933.49 1872.27,-1933.49 1895.27,-1933.49 1940.79,-1933.49 1962.79,-1933.49 1985.79,-1933.49 1850.27,-1907.49 1872.27,-1907.49 1895.27,-1907.49 1940.79,-1907.49 1962.79,-1907.49 1985.79,-1907.49 6215.39,-826.77 6259.84,-826.77 6299.21,-826.77 6184.6,-799.87 6311.02,-791.34 6311.02,-116.14 6311.02,-82.68 6215.39,-47.24 6259.84,-47.24 6299.21,-47.24
+3.3V_QSFP: C5.2 C38.2 C39.2 C40.2 C41.2 C89.2 C96.2 C98.2 C99.2 C101.2 C109.2 C110.2 C111.2 C112.2 C113.2 C114.2 L1.2 L5.1 L6.1 L7.1 L8.1 L9.1 L10.1 R16.2 R42.2 R43.2 R44.2 R45.2 R46.2 R47.2 R52.2 R53.2 TP17.1 U7.6 U8.14 U9.14 U10.6 U11.14 | length 1729.7
  L1-TOP w8: v1(1962.79,-2207.08) 1963.1,-2207.39 C40.2@1963.1,-2219.75 TP17.1@1963.1,-2292.99 ; v1(7819.03,2219.62) v1(7857.61,2219.62) ; U11.14@7887.8,2161.42 7867.13,2161.42 7857.61,2170.93 v1(7857.61,2219.62) ; R53.2@7940.75,2231.46 7946.59,2225.62 R53.2@7948.56,2225.62 ; R53.2@7940.75,2231.5 7926.28,2245.97 7883.96,2245.97 7864.44,2226.45 7863.85,2226.45 C109.2@7857.61,2220.21 ; v1(8216.67,2219.65) v1(8255.25,2219.65) ; U8.14@8285.43,2161.42 8264.76,2161.42 8255.25,2170.93 v1(8255.25,2219.65) ; R43.2@8346.2,2225.62 8344.23,2225.62 8325.76,2244.09 8279.11,2244.09 8255.25,2220.24 v1(8255.25,2219.65) ; v1(8667.48,2220.58) v1(8706.06,2220.58) 8706.06,2170.91 8715.55,2161.42 U9.14@8736.22,2161.42 ; v1(8807.09,2007.87) R46.2@8858.27,2007.87 ; v1(8807.09,2110.24) R45.2@8858.27,2110.24 ; R52.2@8998.03,2066.93 9041.34,2066.93 9053.15,2078.74 v1(9053.15,2105.91) 9010.24,2105.91 9003.94,2112.2 U10.6@9003.94,2122.05 ; R42.2@8998.03,2303.15 9038.39,2303.15 9049.21,2313.98 v1(9049.21,2342.13) 9006.83,2342.13 9003.94,2345.02 U7.6@9003.94,2354.33 ; v1(7857.61,2219.62) C109.2@7857.61,2220.21 ; v1(7857.61,2219.62) C109.2@7857.61,2220.21
  L1-TOP w12: C41.2@1393.47,-2294.41 1355.86,-2294.41 1355.47,-2294.02 1465.23,-2294.02 1529.37,-2358.16 1781.09,-2358.16 1872.27,-2266.99 C39.2@1872.27,-2219.75
  L1-TOP w16: C40.2@1963.1,-2219.75 C40.2@1963.68,-2219.16
  other v1: 1849.97,-2233.08 1871.97,-2233.08 1894.97,-2233.08 1940.79,-2233.08 1962.79,-2233.08 1985.79,-2233.08 1849.97,-2207.08 1871.97,-2207.08 1894.97,-2207.08 1940.79,-2207.08 1985.79,-2207.08 6588.57,1105.21 6633.25,1105.21 6677.94,1105.21 6722.62,1105.21 6767.31,1105.21 6811.99,1105.21 6588.57,1148.52 6633.25,1148.52 6677.94,1148.52 6722.62,1148.52 6767.31,1148.52 6811.99,1148.52 6588.55,2128.83 6633.24,2128.83 6677.92,2128.83 6722.61,2128.83 6767.29,2128.83 6811.98,2128.83 6588.55,2172.14 6633.24,2172.14 6677.92,2172.14 6722.61,2172.14 6767.29,2172.14 6811.98,2172.14
+3.3V_SZG: C59.2 C60.2 C61.2 C62.2 J1.40 J2.40 J4.40 J5.40 J8.40 J23.40 L3.2 R22.2 TP19.1 | length 606.4
  L1-TOP w8: C61.2@524.14,-1915.34 TP19.1@524.14,-1821.04
  L1-TOP w9: C60.2@613.79,-1893.34 C60.2@636.32,-1893.34 ; R22.2@922.74,-1884.95 960.35,-1884.95 C62.2@960.74,-1884.55
  L1-TOP w10: C60.2@602.32,-1903.34 C60.2@614.32,-1915.34
  L1-TOP w12: C60.2@613.79,-1893.34 613.79,-1828.18 633.33,-1808.63 884.93,-1808.63 922.74,-1846.44 R22.2@922.74,-1882.98
  other v1: 1755.94,-2678.11 3606.34,-2678.11 1755.94,-2643.11 3606.34,-2643.11 1755.94,-2608.11 3606.34,-2608.11 501.14,-1928.43 523.14,-1928.43 546.14,-1928.43 591.32,-1928.43 613.32,-1928.43 636.32,-1928.43 501.14,-1902.43 523.14,-1902.25 546.14,-1902.43 591.32,-1902.43 613.32,-1902.43 636.32,-1902.43 5464.68,2607.69 7511.92,2607.69 1551.24,2608.11 3401.64,2608.11 5464.68,2630.69 7511.92,2630.69 1551.24,2643.11 3401.64,2643.11 5464.68,2654.69 7511.92,2654.69 5464.68,2677.69 7511.92,2677.69 1551.24,2678.11 3401.64,2678.11
+3.3VDD: C2.2 MC1.173 MC1.175 R3.2 R4.2 R5.2 R30.2 TP4.1 U1.8 | length 6952.8
  L1-TOP w8: R30.2@1185.04,2405.51 1295.28,2405.51 TP4.1@1417.32,2283.46
  L1-TOP w10: v1(1861.81,1724.41) 1861.81,1697.24 1873.52,1685.54 2248.87,1685.54 2257.87,1694.54 2257.87,1716.54 R3.2@2259.84,1716.54 2275.87,1716.54 2284.87,1725.54 2284.87,1794.54 ; R4.2@2257.87,1794.54 R4.2@2259.84,1794.54 2284.87,1794.54 ; R5.2@2257.87,1872.54 R5.2@2259.84,1872.54 2277.11,1872.54 2284.87,1864.77 2284.87,1794.54
  L1-TOP w11: MC1.173@5029.54,1558.68 5029.54,1502.75 5049.23,1522.43 MC1.175@5049.23,1558.68
  L1-TOP w19: TP4.1@1417.32,2283.46 1551.18,2149.61 1551.18,1913.39 1740.16,1724.41 v1(1861.81,1724.41) ; C2.2@1862.2,1724.41 v1(1861.81,1724.41) ; U1.8@1865.69,1784.26 1864.12,1784.26 1861.81,1781.95 v1(1861.81,1724.41)
  L1-TOP w20: 1551.18,1913.39 1381.9,1913.39 1332.62,1864.11 1332.62,1753.99 2145.67,940.94 4913.39,940.94 5133.86,1161.42 5133.86,1370.08 5118.11,1385.83 5068.91,1385.83 5051.18,1403.56 5051.18,1464.57 5029.54,1486.2 5029.54,1502.75
+5V_SZG: C67.2 C68.2 C69.2 C70.2 J1.2 J2.2 J4.2 J5.2 J8.2 J23.2 L4.2 R26.2 TP20.1 | length 720.5
  L1-TOP w8: v1(523.14,-2228.71) 523.14,-2373.54 TP20.1@566.93,-2417.32 ; R26.2@930.14,-2274.49 C70.2@967.74,-2274.49
  L1-TOP w12: C68.2@614.32,-2215.62 614.32,-2308.93 653.16,-2347.77 892.51,-2347.77 929.74,-2310.54 R26.2@929.74,-2276.06
  L1-TOP w16: C69.2@523.14,-2216.62 C69.2@524.14,-2215.62
  other v1: 1157.44,-2678.11 3007.84,-2678.11 1157.44,-2643.11 3007.84,-2643.11 1157.44,-2608.11 3007.84,-2608.11 501.14,-2228.71 546.14,-2228.71 591.32,-2228.54 613.32,-2228.54 636.32,-2228.54 501.14,-2202.71 523.14,-2202.71 546.14,-2202.71 591.32,-2202.54 613.32,-2202.54 636.32,-2202.54 2149.74,2608.11 4000.14,2608.11 6051.38,2608.38 8098.63,2608.38 6051.38,2631.38 8098.63,2631.38 2149.74,2643.11 4000.14,2643.11 6051.38,2655.38 8098.63,2655.38 2149.74,2678.11 4000.14,2678.11 6051.38,2678.38 8098.63,2678.38
+VDCIN: C33.1 C34.1 C36.1 C37.2 C46.1 C47.1 C57.1 C58.1 J24.1 J24.2 J24.3 J28.1 MC1.1 MC1.2 MC1.3 MC1.4 MC1.5 MC1.6 MC1.7 MC1.8 TP2.1 U3.5 U3.6 U3.22 U3.30 U3.31 | length 476.1
  L1-TOP w10: J28.1@566.93,2503.94 627.86,2503.94 639.67,2492.13 C37.2@850,2492.13 v1(851.97,2492.13) ; 2942.93,1614.17 2988.81,1614.17 3001.98,1601 MC1.7@3001.98,1558.68 3001.98,1516.35 2993.5,1507.87 2968.5,1507.87
  other v1: 1411.47,-2149.59 1456.74,-2149.59 1392.24,-2129.66 1437.06,-2129.66 1476.43,-2129.66 944.27,-2123.66 981.74,-2118.1 1017.18,-2118.1 944.27,-2101.66 1390.47,-2099.56 1417.74,-2099.56 1440.74,-2099.56 1463.99,-2099.56 1486.74,-2099.56 1036.24,-2098.41 1017.18,-2082.68 944.27,-2078.66 981.74,-2078.66 1036.24,-2067.16 1017.18,-2049.63 991.27,-2035.66 1139.74,-1898.39 1115.64,-1893.43 1118.1,-1867.16 1072.29,-1843.33 1123.9,-1843.33 1072.29,-1811.16 1123.9,-1811.16 2763.78,1228.35 2791.34,1228.35 2818.9,1228.35 2846.46,1228.35 2874.03,1228.35 2901.7,1228.35 2763.78,1256.01 2791.34,1256.01 2818.9,1256.01 2846.46,1256.01 2874.03,1256.01 2763.78,1283.68 2791.34,1283.68 2818.9,1283.68 2846.46,1283.68 2763.95,1311.35 2791.51,1311.35 2819.07,1311.35 2763.78,1339.01 2791.34,1339.01 2818.9,1339.01 2763.78,1366.68 2791.34,1366.68 2763.78,1394.35 928.5,2048.28 968.5,2048.28 928.5,2107.28 968.5,2107.28 928.5,2164.78 968.5,2164.78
